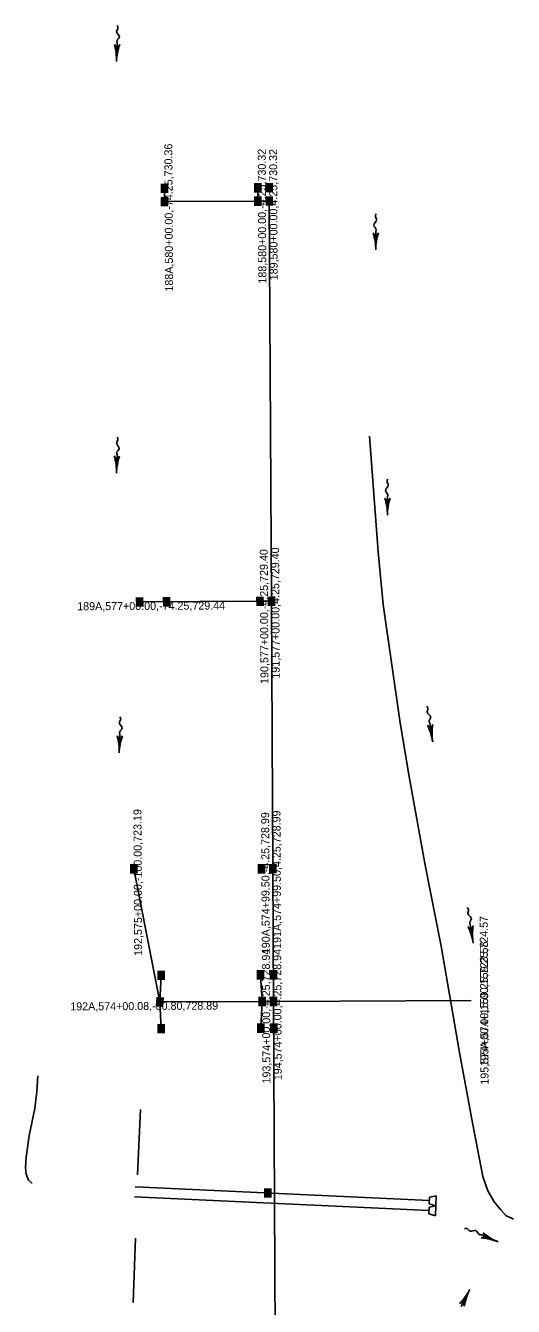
# Model space of a CAD drawing. Extents: x 593481 to 595859, y 150220 to 157407.
# Drawn here: x 594163 to 594529, y 156447 to 157407 of the extents above; entities that cross this region are included whole.
import ezdxf

# ---------------------------------------------------------------- set-up
doc = ezdxf.new("R2010")
doc.units = 0
for name, color, linetype in [('E_PROF_GridMin', 7, 'Continuous'), ('P_ALI_20_Tic', 7, 'Continuous'), ('P_ALI_50_Equation', 7, 'Continuous'), ('P_DRN_Pipes', 7, 'Continuous'), ('P_DRN_SS_UG', 7, 'Continuous')]:
    doc.layers.add(name, color=color, linetype=linetype)

msp = doc.modelspace()

# ---------------------------------------------------------------- linework, layer by layer
at = {"layer": 'E_PROF_GridMin'}
for p, q in [((594267.35, 157284.82), (594267.4, 157274.82)), ((594337.4, 157275.17), (594337.35, 157285.17)), ((594267.4, 157274.82), (594337.4, 157275.17)), ((594337.4, 157275.17), (594345.9, 157275.22)), ((594345.9, 157275.22), (594347.44, 156975.22)), ((594248.68, 156974.72), (594338.94, 156975.18)), ((594338.94, 156975.18), (594347.44, 156975.22)), ((594347.44, 156975.22), (594348.98, 156675.23)), ((594244.22, 156774.69), (594263.93, 156674.87)), ((594263.93, 156674.87), (594264.83, 156694.79)), ((594340.48, 156675.18), (594339.38, 156695.18)), ((594263.93, 156674.87), (594340.48, 156675.18)), ((594263.93, 156674.87), (594264.84, 156654.79)), ((594340.48, 156675.18), (594339.58, 156655.18)), ((594340.48, 156675.18), (594349.98, 156675.23)), ((594350.52, 156375.23), (594348.98, 156675.23)), ((594349.98, 156675.23), (594497.36, 156675.99))]:
    msp.add_line(p, q, dxfattribs=at)
for points in [[(594528.92, 156512.09), (594523.22, 156514.81), (594519.47, 156519.07), (594514.44, 156525.15), (594509.64, 156533.2), (594506.08, 156544.08), (594498.37, 156584.35), (594488.59, 156636.93), (594474.73, 156716.61), (594462.78, 156777.43), (594450.93, 156842.33), (594444.05, 156884.21), (594431.21, 156972.86), (594427.45, 157012.21), (594420.91, 157099.06)], [(594168.16, 156538.76), (594165.24, 156541.17), (594163.58, 156545.8), (594163.17, 156550.75), (594163.54, 156558.44), (594165.9, 156574.68), (594169.98, 156595.1), (594171.64, 156607.71), (594172.22, 156619.6)], [(594247.01, 156545.3), (594249.22, 156594.27)], [(594245.47, 156497.73), (594243.85, 156449.49)]]:
    msp.add_lwpolyline(points, dxfattribs=at)
at = {"layer": 'P_ALI_20_Tic'}
for p, q in [((594231.3, 157379.73), (594231.76, 157393.85)), ((594425.77, 157238.61), (594425.77, 157252.74)), ((594231.25, 157071.35), (594231.71, 157085.47)), ((594434.49, 157039.76), (594434.49, 157053.89)), ((594233.34, 156861.58), (594233.8, 156875.7)), ((594468.4, 156869.92), (594466.21, 156883.87)), ((594498.81, 156718.98), (594496.61, 156732.94)), ((594517.39, 156495.04), (594504.34, 156500.44)), ((594496.16, 156459.25), (594489.74, 156446.66))]:
    msp.add_line(p, q, dxfattribs=at)
for points in [[(594229.71, 157392.59), (594231.61, 157389.32), (594233.71, 157392.46)], [(594427.77, 157251.4), (594425.77, 157248.2), (594423.77, 157251.41)], [(594229.67, 157084.2), (594231.56, 157080.94), (594233.67, 157084.08)], [(594436.49, 157052.56), (594434.49, 157049.36), (594432.49, 157052.56)], [(594464.44, 156882.25), (594466.91, 156879.4), (594468.39, 156882.87)], [(594231.75, 156874.43), (594233.65, 156871.17), (594235.75, 156874.31)], [(594494.84, 156731.31), (594497.31, 156728.46), (594498.79, 156731.93)], [(594504.8, 156498.08), (594508.52, 156498.7), (594506.33, 156501.78)], [(594492.13, 156446.94), (594491.8, 156450.7), (594488.56, 156448.76)]]:
    msp.add_lwpolyline(points, dxfattribs=at)
for centre, start, end in [((594189.36, 157381.1), 358.13392, 15.89624), ((594273.23, 157378.37), 160.3716, 178.13392), ((594383.81, 157238.61), 0, 17.76232), ((594467.72, 157238.61), 162.23768, 180), ((594189.32, 157072.71), 358.13392, 15.89624), ((594273.19, 157069.98), 160.3716, 178.13392), ((594392.54, 157039.76), 0, 17.76232), ((594476.45, 157039.76), 162.23768, 180), ((594426.96, 156863.39), 8.94535, 26.70767), ((594509.85, 156876.44), 171.18303, 188.94535), ((594191.4, 156862.95), 358.13392, 15.89624), ((594275.27, 156860.21), 160.3716, 178.13392), ((594457.36, 156712.46), 8.94535, 26.70767), ((594540.26, 156725.5), 171.18303, 188.94535), ((594533.42, 156533.82), 229.77978, 247.5421), ((594501.37, 156456.27), 67.5421, 85.30442), ((594458.79, 156478.33), 315.19309, 332.95541), ((594533.53, 156440.17), 152.95541, 170.71773)]:
    msp.add_arc(centre, 41.96, start, end, dxfattribs=at)
for points in [[(594231.76, 157393.85), (594231.47, 157394.65), (594233.47, 157398.2), (594231.4, 157402.19), (594232.44, 157404.98), (594231.86, 157406.73)], [(594425.77, 157252.74), (594426.08, 157253.52), (594424.2, 157257.13), (594426.39, 157261.06), (594425.45, 157263.88), (594426.08, 157265.61)], [(594231.71, 157085.47), (594231.42, 157086.26), (594233.42, 157089.81), (594231.36, 157093.8), (594232.39, 157096.6), (594231.82, 157098.34)], [(594434.49, 157053.89), (594434.81, 157054.67), (594432.92, 157058.28), (594435.12, 157062.21), (594434.18, 157065.03), (594434.81, 157066.76)], [(594466.21, 156883.87), (594465.78, 156884.6), (594467.07, 156888.46), (594464.29, 156891.99), (594464.78, 156894.93), (594463.9, 156896.54)], [(594233.8, 156875.7), (594233.51, 156876.5), (594235.51, 156880.04), (594233.44, 156884.04), (594234.47, 156886.83), (594233.9, 156888.58)], [(594496.61, 156732.94), (594496.18, 156733.66), (594497.48, 156737.52), (594494.7, 156741.06), (594495.19, 156743.99), (594494.3, 156745.6)], [(594504.34, 156500.44), (594503.49, 156500.45), (594500.87, 156503.57), (594496.41, 156503.04), (594494.16, 156504.99), (594492.32, 156505.06)]]:
    msp.add_spline(points, degree=3, dxfattribs=at)
at = {"layer": 'P_DRN_Pipes'}
for p, q in [((594245.39, 156536.21), (594465.96, 156526.08)), ((594471.13, 156529.59), (594466.08, 156528.58)), ((594470.79, 156522.1), (594471.13, 156529.59)), ((594244.94, 156528.76), (594465.62, 156518.63)), ((594465.74, 156521.12), (594465.51, 156516.13)), ((594470.79, 156522.14), (594465.74, 156521.12)), ((594466.08, 156528.58), (594465.85, 156523.58)), ((594465.85, 156523.58), (594470.79, 156522.1)), ((594470.44, 156514.65), (594470.79, 156522.14)), ((594465.51, 156516.13), (594470.44, 156514.65))]:
    msp.add_line(p, q, dxfattribs=at)
at = {"layer": 'P_DRN_SS_UG'}
for p, q in [((594265.12, 157281.37), (594265.08, 157288.24)), ((594266.02, 157281.37), (594265.98, 157288.25)), ((594266.92, 157281.38), (594266.88, 157288.25)), ((594267.82, 157281.38), (594267.78, 157288.26)), ((594268.72, 157281.38), (594268.68, 157288.26)), ((594269.62, 157281.39), (594269.58, 157288.26)), ((594335.12, 157281.73), (594335.08, 157288.6)), ((594336.02, 157281.73), (594335.98, 157288.61)), ((594336.92, 157281.73), (594336.88, 157288.61)), ((594337.82, 157281.74), (594337.78, 157288.61)), ((594338.72, 157281.74), (594338.68, 157288.62)), ((594339.62, 157281.75), (594339.58, 157288.62)), ((594343.65, 157281.78), (594343.61, 157288.65)), ((594344.55, 157281.78), (594344.51, 157288.66)), ((594345.45, 157281.79), (594345.41, 157288.66)), ((594346.35, 157281.79), (594346.31, 157288.67)), ((594347.25, 157281.8), (594347.21, 157288.67)), ((594348.15, 157281.8), (594348.11, 157288.68)), ((594265.17, 157271.37), (594265.14, 157278.24)), ((594266.07, 157271.37), (594266.04, 157278.25)), ((594266.97, 157271.38), (594266.94, 157278.25)), ((594267.87, 157271.38), (594267.84, 157278.26)), ((594268.77, 157271.38), (594268.74, 157278.26)), ((594269.67, 157271.39), (594269.64, 157278.26)), ((594335.17, 157271.73), (594335.13, 157278.6)), ((594336.07, 157271.73), (594336.03, 157278.61)), ((594336.97, 157271.73), (594336.93, 157278.61)), ((594337.87, 157271.74), (594337.83, 157278.61)), ((594338.77, 157271.74), (594338.73, 157278.62)), ((594339.67, 157271.75), (594339.63, 157278.62)), ((594343.67, 157271.77), (594343.63, 157278.64)), ((594344.57, 157271.77), (594344.53, 157278.65)), ((594345.47, 157271.78), (594345.43, 157278.65)), ((594346.37, 157271.78), (594346.33, 157278.66)), ((594347.27, 157271.79), (594347.23, 157278.66)), ((594348.17, 157271.79), (594348.13, 157278.67)), ((594246.45, 156971.27), (594246.41, 156978.14)), ((594247.35, 156971.27), (594247.31, 156978.15)), ((594248.25, 156971.28), (594248.21, 156978.15)), ((594249.15, 156971.28), (594249.11, 156978.16)), ((594250.05, 156971.28), (594250.01, 156978.16)), ((594250.95, 156971.29), (594250.91, 156978.16)), ((594266.71, 156971.37), (594266.68, 156978.25)), ((594267.61, 156971.37), (594267.58, 156978.25)), ((594268.51, 156971.38), (594268.48, 156978.25)), ((594269.41, 156971.38), (594269.38, 156978.26)), ((594270.31, 156971.39), (594270.28, 156978.26)), ((594271.21, 156971.39), (594271.18, 156978.27)), ((594336.71, 156971.73), (594336.67, 156978.6)), ((594337.61, 156971.73), (594337.57, 156978.61)), ((594338.51, 156971.74), (594338.47, 156978.61)), ((594339.41, 156971.74), (594339.37, 156978.62)), ((594340.31, 156971.75), (594340.27, 156978.62)), ((594341.21, 156971.75), (594341.17, 156978.63)), ((594345.21, 156971.77), (594345.17, 156978.65)), ((594346.11, 156971.78), (594346.07, 156978.65)), ((594347.01, 156971.78), (594346.97, 156978.66)), ((594347.91, 156971.79), (594347.87, 156978.66)), ((594348.81, 156971.79), (594348.77, 156978.67)), ((594349.71, 156971.8), (594349.67, 156978.67)), ((594241.99, 156771.24), (594241.95, 156778.12)), ((594242.89, 156771.25), (594242.85, 156778.12)), ((594243.79, 156771.25), (594243.75, 156778.12)), ((594244.69, 156771.25), (594244.65, 156778.13)), ((594245.59, 156771.26), (594245.55, 156778.13)), ((594246.49, 156771.26), (594246.45, 156778.14)), ((594337.74, 156771.23), (594337.7, 156778.11)), ((594338.64, 156771.24), (594338.6, 156778.11)), ((594339.54, 156771.24), (594339.5, 156778.12)), ((594340.44, 156771.25), (594340.4, 156778.12)), ((594341.34, 156771.25), (594341.3, 156778.13)), ((594342.24, 156771.26), (594342.2, 156778.13)), ((594346.24, 156771.28), (594346.2, 156778.15)), ((594347.14, 156771.28), (594347.1, 156778.16)), ((594348.04, 156771.29), (594348, 156778.16)), ((594348.94, 156771.29), (594348.9, 156778.16)), ((594349.84, 156771.29), (594349.8, 156778.17)), ((594350.74, 156771.3), (594350.7, 156778.17)), ((594262.6, 156691.35), (594262.56, 156698.22)), ((594263.5, 156691.35), (594263.46, 156698.23)), ((594264.4, 156691.35), (594264.36, 156698.23)), ((594265.3, 156691.36), (594265.26, 156698.23)), ((594266.2, 156691.36), (594266.16, 156698.24)), ((594267.1, 156691.37), (594267.06, 156698.24)), ((594337.15, 156691.73), (594337.11, 156698.6)), ((594338.05, 156691.73), (594338.01, 156698.61)), ((594338.95, 156691.74), (594338.91, 156698.61)), ((594339.85, 156691.74), (594339.81, 156698.62)), ((594340.75, 156691.75), (594340.71, 156698.62)), ((594341.65, 156691.75), (594341.61, 156698.63)), ((594346.82, 156691.79), (594346.78, 156698.66)), ((594347.72, 156691.79), (594347.68, 156698.67)), ((594348.62, 156691.8), (594348.58, 156698.67)), ((594349.52, 156691.8), (594349.48, 156698.68)), ((594350.42, 156691.81), (594350.38, 156698.68)), ((594351.32, 156691.81), (594351.28, 156698.69)), ((594261.43, 156671.61), (594261.94, 156678.46)), ((594262.33, 156671.54), (594262.84, 156678.39)), ((594263.22, 156671.47), (594263.74, 156678.33)), ((594264.12, 156671.4), (594264.63, 156678.26)), ((594265.02, 156671.34), (594265.53, 156678.19)), ((594265.92, 156671.27), (594266.43, 156678.13)), ((594338.25, 156671.73), (594338.21, 156678.61)), ((594339.15, 156671.74), (594339.11, 156678.61)), ((594340.05, 156671.74), (594340.01, 156678.62)), ((594340.95, 156671.75), (594340.91, 156678.62)), ((594341.85, 156671.75), (594341.81, 156678.63)), ((594342.75, 156671.76), (594342.71, 156678.63)), ((594346.75, 156671.78), (594346.71, 156678.65)), ((594347.65, 156671.78), (594347.61, 156678.66)), ((594348.55, 156671.79), (594348.51, 156678.66)), ((594349.45, 156671.79), (594349.41, 156678.67)), ((594350.35, 156671.8), (594350.31, 156678.67)), ((594351.25, 156671.8), (594351.21, 156678.68)), ((594262.6, 156651.35), (594262.57, 156658.22)), ((594263.5, 156651.35), (594263.47, 156658.22)), ((594264.4, 156651.35), (594264.37, 156658.23)), ((594265.3, 156651.36), (594265.27, 156658.23)), ((594266.2, 156651.36), (594266.17, 156658.24)), ((594267.1, 156651.37), (594267.07, 156658.24)), ((594337.35, 156651.73), (594337.32, 156658.6)), ((594338.25, 156651.73), (594338.22, 156658.61)), ((594339.15, 156651.74), (594339.12, 156658.61)), ((594340.05, 156651.74), (594340.02, 156658.62)), ((594340.95, 156651.75), (594340.92, 156658.62)), ((594341.85, 156651.75), (594341.82, 156658.63)), ((594347.16, 156651.79), (594347.13, 156658.66)), ((594348.06, 156651.79), (594348.03, 156658.67)), ((594348.96, 156651.8), (594348.93, 156658.67)), ((594349.86, 156651.8), (594349.83, 156658.68)), ((594350.76, 156651.81), (594350.73, 156658.68)), ((594351.66, 156651.81), (594351.63, 156658.69)), ((594342.57, 156528.19), (594342.53, 156535.07)), ((594343.47, 156528.2), (594343.43, 156535.07)), ((594344.37, 156528.2), (594344.33, 156535.08)), ((594345.27, 156528.21), (594345.23, 156535.08)), ((594346.17, 156528.21), (594346.13, 156535.09)), ((594347.07, 156528.22), (594347.03, 156535.09))]:
    msp.add_line(p, q, dxfattribs=at)
for points in [[(594268.36, 157283.82), (594268.35, 157285.82), (594266.35, 157285.81), (594266.36, 157283.81)], [(594338.36, 157284.18), (594338.35, 157286.18), (594336.35, 157286.17), (594336.36, 157284.17)], [(594346.89, 157284.23), (594346.88, 157286.23), (594344.88, 157286.22), (594344.89, 157284.22)], [(594268.41, 157273.82), (594268.4, 157275.82), (594266.4, 157275.81), (594266.41, 157273.81)], [(594338.41, 157274.18), (594338.4, 157276.18), (594336.4, 157276.17), (594336.41, 157274.17)], [(594346.91, 157274.22), (594346.9, 157276.22), (594344.9, 157276.21), (594344.91, 157274.21)], [(594249.68, 156973.72), (594249.67, 156975.72), (594247.67, 156975.71), (594247.68, 156973.71)], [(594269.95, 156973.82), (594269.94, 156975.82), (594267.94, 156975.81), (594267.95, 156973.81)], [(594339.95, 156974.18), (594339.94, 156976.18), (594337.94, 156976.17), (594337.95, 156974.17)], [(594348.45, 156974.23), (594348.44, 156976.23), (594346.44, 156976.22), (594346.45, 156974.22)], [(594245.23, 156773.69), (594245.22, 156775.69), (594243.22, 156775.68), (594243.23, 156773.68)], [(594340.98, 156773.69), (594340.97, 156775.69), (594338.97, 156775.68), (594338.98, 156773.68)], [(594349.48, 156773.73), (594349.47, 156775.73), (594347.47, 156775.72), (594347.48, 156773.72)], [(594265.84, 156693.8), (594265.83, 156695.8), (594263.83, 156695.79), (594263.84, 156693.79)], [(594340.38, 156694.18), (594340.37, 156696.18), (594338.37, 156696.17), (594338.38, 156694.17)], [(594350.06, 156694.24), (594350.05, 156696.24), (594348.05, 156696.23), (594348.06, 156694.23)], [(594264.85, 156673.79), (594265, 156675.79), (594263.01, 156675.94), (594262.86, 156673.94)], [(594341.49, 156674.19), (594341.48, 156676.19), (594339.48, 156676.18), (594339.49, 156674.18)], [(594349.99, 156674.23), (594349.98, 156676.23), (594347.98, 156676.22), (594347.99, 156674.22)], [(594265.84, 156653.8), (594265.83, 156655.8), (594263.83, 156655.79), (594263.84, 156653.79)], [(594340.59, 156654.18), (594340.58, 156656.18), (594338.58, 156656.17), (594338.59, 156654.17)], [(594350.4, 156654.24), (594350.39, 156656.24), (594348.39, 156656.23), (594348.4, 156654.23)], [(594345.8, 156530.65), (594345.79, 156532.65), (594343.79, 156532.64), (594343.8, 156530.64)]]:
    msp.add_lwpolyline(points, close=True, dxfattribs=at)

# ---------------------------------------------------------------- texts
at = {"layer": 'P_ALI_50_Equation'}
for s, rotation, p in [('188A,580+00.00,-74.25,730.36', 90.29409, (594273.75, 157207.39)), ('188,580+00.00,-4.25,730.32', 90.29409, (594343.72, 157213.37)), ('189,580+00.00,4.25,730.32', 90.29409, (594352.21, 157215.82)), ('190,577+00.00,-4.25,729.40', 90.29409, (594345.26, 156913.25)), ('191,577+00.00,4.25,729.40', 90.29409, (594353.74, 156917.22)), ('189A,577+00.00,-74.25,729.44', 0.29409, (594201.89, 156968.48)), ('192,575+00.00,-100.00,723.19', 90.29409, (594250.56, 156709.43)), ('191A,574+99.50,4.25,728.99', 90.29409, (594354.78, 156714.67)), ('190A,574+99.50,-4.25,728.99', 90.29409, (594346.3, 156710.7)), ('195A,574+15.00,159.25,724.57', 90.29409, (594510.23, 156626.66)), ('193,574+00.00,-4.25,728.94', 90.29409, (594346.8, 156613.75)), ('194,574+00.00,4.25,728.94', 90.29409, (594355.28, 156616.25)), ('195,574+00.00,159.25,723.58', 90.29409, (594510.3, 156612.89)), ('192A,574+00.08,-80.80,728.89', 0.29409, (594196.69, 156668.52))]:
    msp.add_text(s, height=6, rotation=rotation, dxfattribs=at).set_placement(p)

doc.saveas('drawing.dxf')
